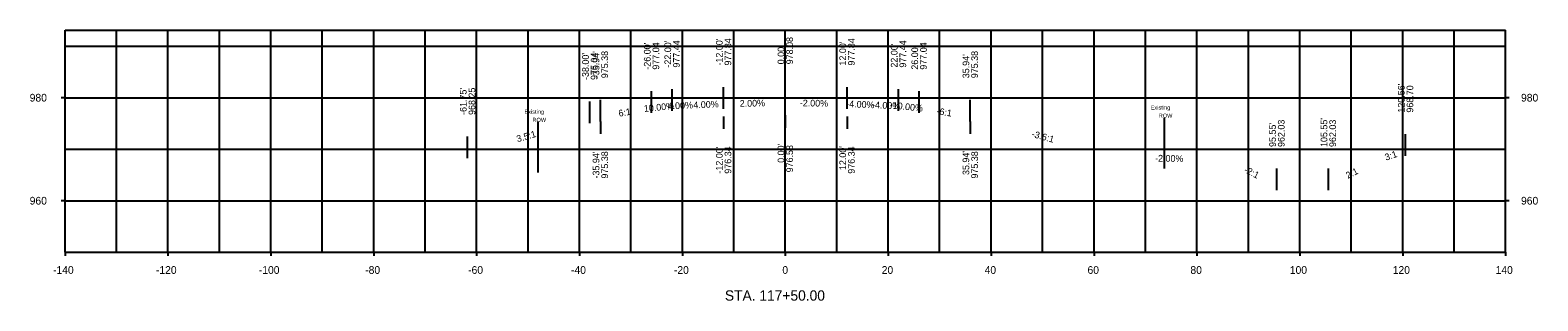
# Model space of a CAD drawing. Extents: x -147 to 146, y 941 to 993.
import ezdxf

# ---------------------------------------------------------------- set-up
doc = ezdxf.new("R2010")
doc.units = 0
for name, color, linetype in [('Default', 7, 'Continuous'), ('dsnCellElements', 7, 'Continuous'), ('SheetBorder', 7, 'Continuous'), ('SheetGridMajor', 7, 'Continuous'), ('SheetGridMinor', 7, 'Continuous'), ('Text', 7, 'Continuous')]:
    doc.layers.add(name, color=color, linetype=linetype)

msp = doc.modelspace()

# ---------------------------------------------------------------- linework, layer by layer
at = {"layer": 'dsnCellElements'}
for p, q in [((73.65, 976.12), (73.65, 966.27)), ((-48.08, 975.31), (-48.08, 965.46))]:
    msp.add_line(p, q, dxfattribs=at)
at = {"layer": 'SheetBorder'}
for p, q in [((-140, 993.1), (140, 993.1)), ((-140, 950), (-140, 993.1)), ((140, 950), (140, 993.1)), ((-140, 950), (140, 950))]:
    msp.add_line(p, q, dxfattribs=at)
at = {"layer": 'SheetGridMajor'}
for p, q in [((-120, 950), (-120, 993.1)), ((-100, 950), (-100, 993.1)), ((-80, 950), (-80, 993.1)), ((-60, 950), (-60, 993.1)), ((-40, 950), (-40, 993.1)), ((-20, 950), (-20, 993.1)), ((0, 950), (0, 993.1)), ((20, 950), (20, 993.1)), ((40, 950), (40, 993.1)), ((60, 950), (60, 993.1)), ((80, 950), (80, 993.1)), ((100, 950), (100, 993.1)), ((120, 950), (120, 993.1)), ((-140, 980), (-140.72, 980)), ((-140, 980), (140, 980)), ((140.72, 980), (140, 980)), ((-140, 960), (-140.72, 960)), ((-140, 960), (140, 960)), ((140.72, 960), (140, 960)), ((-140, 950), (-140, 949.28)), ((-120, 950), (-120, 949.28)), ((-100, 950), (-100, 949.28)), ((-80, 950), (-80, 949.28)), ((-60, 950), (-60, 949.28)), ((-40, 950), (-40, 949.28)), ((-20, 950), (-20, 949.28)), ((0, 950), (0, 949.28)), ((20, 950), (20, 949.28)), ((40, 950), (40, 949.28)), ((60, 950), (60, 949.28)), ((80, 950), (80, 949.28)), ((100, 950), (100, 949.28)), ((120, 950), (120, 949.28)), ((140, 950), (140, 949.28))]:
    msp.add_line(p, q, dxfattribs=at)
at = {"layer": 'SheetGridMinor'}
for p, q in [((-130, 950), (-130, 993.1)), ((-110, 950), (-110, 993.1)), ((-90, 950), (-90, 993.1)), ((-70, 950), (-70, 993.1)), ((-50, 950), (-50, 993.1)), ((-30, 950), (-30, 993.1)), ((-10, 950), (-10, 993.1)), ((10, 950), (10, 993.1)), ((30, 950), (30, 993.1)), ((50, 950), (50, 993.1)), ((70, 950), (70, 993.1)), ((90, 950), (90, 993.1)), ((110, 950), (110, 993.1)), ((130, 950), (130, 993.1)), ((-140, 990), (140, 990)), ((-140, 970), (140, 970))]:
    msp.add_line(p, q, dxfattribs=at)
at = {"layer": 'Text'}
for p, q in [((-12, 977.84), (-12, 982.04)), ((-12, 977.84), (-12, 982.04)), ((0, 978.08), (0, 982.28)), ((0, 978.08), (0, 982.28)), ((0, 978.08), (0, 982.28)), ((0, 978.08), (0, 982.28)), ((12, 977.84), (12, 982.04)), ((12, 977.84), (12, 982.04)), ((-38, 975.04), (-38, 979.24)), ((-35.94, 975.38), (-35.94, 979.58)), ((-26, 977.04), (-26, 981.24)), ((-22, 977.44), (-22, 981.64)), ((22, 977.44), (22, 981.64)), ((26, 977.04), (26, 981.24)), ((35.94, 975.38), (35.94, 979.58)), ((35.94, 975.38), (35.94, 979.58)), ((-12, 976.34), (-12, 973.94)), ((0, 976.58), (0, 974.18)), ((0, 976.58), (0, 974.18)), ((0, 976.58), (0, 974.18)), ((12, 976.34), (12, 973.94)), ((-35.94, 975.38), (-35.94, 972.98)), ((35.94, 975.38), (35.94, 972.98)), ((-61.75, 968.25), (-61.75, 972.45)), ((120.56, 968.7), (120.56, 972.9)), ((95.55, 962.03), (95.55, 966.23)), ((105.55, 962.03), (105.55, 966.23))]:
    msp.add_line(p, q, dxfattribs=at)

# ---------------------------------------------------------------- texts
at = {"layer": 'Default'}
for s, height, p in [('980', 1.5, (-146.87, 979.25)), ('980', 1.5, (143, 979.25)), ('960', 1.5, (-146.87, 959.25)), ('960', 1.5, (143, 959.25)), ('-140', 1.5, (-142.33, 945.8)), ('-120', 1.5, (-122.33, 945.8)), ('-100', 1.5, (-102.33, 945.8)), ('-80', 1.5, (-81.65, 945.8)), ('-60', 1.5, (-61.65, 945.8)), ('-40', 1.5, (-41.65, 945.8)), ('-20', 1.5, (-21.65, 945.8)), ('0', 1.5, (-0.58, 945.8)), ('20', 1.5, (18.74, 945.8)), ('40', 1.5, (38.74, 945.8)), ('60', 1.5, (58.74, 945.8)), ('80', 1.5, (78.74, 945.8)), ('100', 1.5, (98.06, 945.8)), ('120', 1.5, (118.06, 945.8)), ('140', 1.5, (138.06, 945.8)), ('STA. 117+50.00', 2.004, (-11.74, 940.6))]:
    msp.add_text(s, height=height, dxfattribs=at).set_placement(p)
at = {"layer": 'dsnCellElements'}
for s, p in [('Existing', (-50.7, 976.88)), ('ROW', (-49.15, 975.31)), ('Existing', (71.03, 977.69)), ('ROW', (72.58, 976.12))]:
    msp.add_text(s, height=0.787, dxfattribs=at).set_placement(p)
at = {"layer": 'Text'}
for s, rotation, p in [("-26.00'", 90, (-26.19, 985.44)), ('977.04', 90, (-24.51, 985.44)), ("-22.00'", 90, (-22.19, 985.84)), ('977.44', 90, (-20.51, 985.84)), ("-12.00'", 90, (-12.19, 986.24)), ("-12.00'", 90, (-12.19, 986.24)), ('977.84', 90, (-10.51, 986.24)), ('977.84', 90, (-10.51, 986.24)), ('978.08', 90, (1.49, 986.48)), ('978.08', 90, (1.49, 986.48)), ('978.08', 90, (1.49, 986.48)), ('978.08', 90, (1.49, 986.48)), ("12.00'", 90, (11.81, 986.24)), ("12.00'", 90, (11.81, 986.24)), ('977.84', 90, (13.49, 986.24)), ('977.84', 90, (13.49, 986.24)), ('977.44', 90, (23.49, 985.84)), ('977.04', 90, (27.49, 985.44)), ("-38.00'", 90, (-38.19, 983.44)), ('975.04', 90, (-36.51, 983.44)), ("-35.94'", 90, (-36.14, 983.78)), ('975.38', 90, (-34.45, 983.78)), ("0.00'", 90, (-0.19, 986.48)), ("0.00'", 90, (-0.19, 986.48)), ("0.00'", 90, (-0.19, 986.48)), ("0.00'", 90, (-0.19, 986.48)), ("22.00'", 90, (21.81, 985.84)), ("26.00'", 90, (25.81, 985.44)), ("35.94'", 90, (35.75, 983.78)), ("35.94'", 90, (35.75, 983.78)), ('975.38', 90, (37.44, 983.78)), ('975.38', 90, (37.44, 983.78)), ("-61.75'", 90, (-61.95, 976.65)), ('968.25', 90, (-60.26, 976.65)), ("120.56'", 90, (120.37, 977.1)), ('968.70', 90, (122.05, 977.1)), ('10.00%', 5.7106, (-27.42, 977.22)), ('4.00%', 2.2906, (-22.85, 977.73)), ('4.00%', 2.2906, (-17.85, 977.93)), ('2.00%', 1.1458, (-8.85, 978.23)), ('-2.00%', 358.8542, (2.81, 978.35)), ('-4.00%', 357.7094, (11.82, 978.17)), ('-4.00%', 357.7094, (16.82, 977.97)), ('-10.00%', 354.2894, (20.25, 977.94)), ('6:1', 9.4642, (-32.31, 976.31)), ('-6:1', 350.5358, (29.31, 976.81)), ("105.55'", 90, (105.35, 970.43)), ('3.5:1', 15.9446, (-52.04, 971.35)), ('-3.6:1', 344.5089, (47.78, 972.42)), ("95.55'", 90, (95.35, 970.43)), ('962.03', 90, (97.04, 970.43)), ('962.03', 90, (107.04, 970.43)), ("-12.00'", 90, (-12.19, 965.27)), ('976.34', 90, (-10.51, 965.24)), ("0.00'", 90, (-0.19, 967.36)), ("0.00'", 90, (-0.19, 967.36)), ("0.00'", 90, (-0.19, 967.36)), ('976.58', 90, (1.49, 965.5)), ('976.58', 90, (1.49, 965.5)), ('976.58', 90, (1.49, 965.5)), ("12.00'", 90, (11.81, 965.95)), ('976.34', 90, (13.49, 965.24)), ("-35.94'", 90, (-36.14, 964.31)), ('975.38', 90, (-34.45, 964.3)), ("35.94'", 90, (35.75, 964.99)), ('975.38', 90, (37.44, 964.3)), ('-2.00%', 358.8542, (71.87, 967.62)), ('3:1', 18.4332, (116.76, 967.76)), ('-2:1', 333.4349, (89.03, 965.59)), ('2:1', 26.5651, (109.33, 964.22))]:
    msp.add_text(s, height=1.296, rotation=rotation, dxfattribs=at).set_placement(p)

doc.saveas('drawing.dxf')
